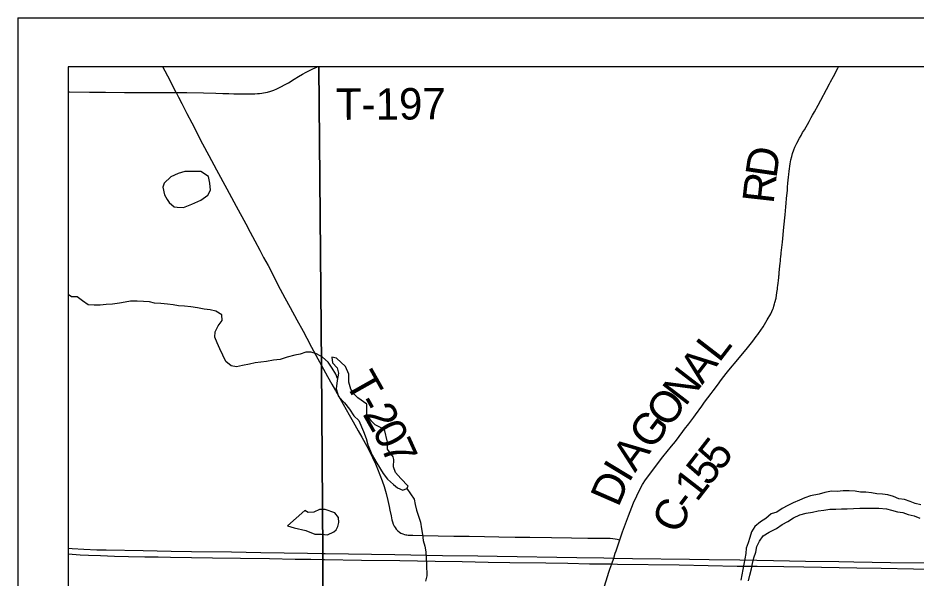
# Model space of a CAD drawing. Extents: x 0 to 34, y 0 to 22.
# Drawn here: x 12.556 to 14.178, y 15.798 to 16.81 of the extents above; entities that cross this region are included whole.
import ezdxf

# ---------------------------------------------------------------- set-up
doc = ezdxf.new("R2010")
doc.units = 0
for name, color, linetype in [('GM_X_City_Street', 7, 'Continuous'), ('GM_X_Corporation', 7, 'Continuous'), ('GM_X_County_Road', 7, 'Continuous'), ('GM_X_County_Road_Text', 7, 'Continuous'), ('GM_X_Interstate_Route', 7, 'Continuous'), ('GM_X_Major_River', 7, 'Continuous'), ('GM_X_Minor_Lake', 7, 'Continuous'), ('GM_X_Minor_River', 7, 'Continuous'), ('GM_X_Township_Road', 7, 'Continuous'), ('GM_X_Township_Road_Text', 7, 'Continuous'), ('SH_Data', 7, 'Continuous')]:
    doc.layers.add(name, color=color, linetype=linetype)

msp = doc.modelspace()

# ---------------------------------------------------------------- linework, layer by layer
at = {"layer": 'GM_X_City_Street'}
msp.add_lwpolyline([(12.842, 16.6752), (12.8266, 16.7044), (12.8217, 16.7135), (12.8174, 16.7214)], dxfattribs=at)
at = {"layer": 'GM_X_Corporation'}
for points in [[(13.1081, 15.4063), (13.1066, 15.8324), (13.1066, 15.8434), (13.1041, 16.1828), (13.0992, 16.7214), (12.6467, 16.7214), (12.6467, 12.6578)], [(13.1082, 15.4033), (13.1066, 15.8324), (13.1066, 15.8434), (13.1041, 16.1828), (13.0992, 16.7214), (12.6467, 16.7214), (12.6467, 12.6578)], [(18.6549, 16.7214), (13.0992, 16.7214), (13.1041, 16.1828), (13.1066, 15.8434), (13.1066, 15.8324), (13.1082, 15.4033)]]:
    msp.add_lwpolyline(points, dxfattribs=at)
at = {"layer": 'GM_X_County_Road'}
for points in [[(13.6429, 15.8675), (13.6477, 15.8816), (13.6584, 15.9108), (13.6677, 15.9339), (13.6734, 15.9471), (13.6789, 15.9583), (13.6838, 15.967), (13.6896, 15.9759), (13.7078, 16.0004), (13.7146, 16.0092), (13.7208, 16.0171), (13.7364, 16.0364), (13.7433, 16.0452), (13.7568, 16.063), (13.7598, 16.067), (13.7675, 16.0768), (13.7769, 16.0891), (13.7799, 16.0931), (13.7911, 16.1087), (13.7961, 16.1159), (13.8079, 16.1318), (13.8113, 16.1363), (13.8191, 16.1468), (13.8265, 16.1568), (13.835, 16.1675), (13.84, 16.1738), (13.8561, 16.1928), (13.8734, 16.214), (13.883, 16.2262), (13.8894, 16.2345), (13.892, 16.238), (13.8987, 16.2476), (13.9004, 16.2502), (13.9017, 16.2523), (13.9043, 16.2565), (13.909, 16.2645), (13.9157, 16.2757), (13.9195, 16.2841), (13.9204, 16.2864), (13.9213, 16.2893), (13.9225, 16.2935), (13.9232, 16.2958), (13.9251, 16.3036), (13.9266, 16.314), (13.9271, 16.3171), (13.9275, 16.3202), (13.9279, 16.3232), (13.9284, 16.3268), (13.9289, 16.3311), (13.9295, 16.3359), (13.93, 16.3408), (13.9303, 16.3439), (13.9305, 16.3458), (13.931, 16.35), (13.9316, 16.3556), (13.9322, 16.3623), (13.9327, 16.3666), (13.9331, 16.371), (13.9334, 16.374), (13.9339, 16.3789), (13.9343, 16.3832), (13.9345, 16.3856), (13.9367, 16.4046), (13.9394, 16.4318), (13.9413, 16.454), (13.9428, 16.4689), (13.9435, 16.4756), (13.9442, 16.4837), (13.9456, 16.4985), (13.9461, 16.5041), (13.9467, 16.5115), (13.9476, 16.5221), (13.9482, 16.527), (13.949, 16.5332), (13.9507, 16.5461), (13.9521, 16.5535), (13.9535, 16.5596), (13.9549, 16.565), (13.9572, 16.5715), (13.9592, 16.5762), (13.9628, 16.5834), (13.9677, 16.5928), (13.9704, 16.5977), (13.9729, 16.6027), (13.9763, 16.6079), (13.9849, 16.623), (13.9888, 16.63), (13.9912, 16.6343), (13.9945, 16.6403), (14.001, 16.6523), (14.006, 16.6616), (14.016, 16.6803), (14.0216, 16.6907), (14.0237, 16.6945), (14.0289, 16.7043), (14.0366, 16.7189), (14.0379, 16.7214)], [(13.6098, 15.7602), (13.61, 15.7612), (13.6125, 15.7722), (13.6149, 15.7812), (13.6161, 15.7854), (13.6173, 15.7895), (13.6184, 15.7931), (13.6234, 15.8091), (13.6252, 15.8144), (13.6284, 15.8238), (13.6319, 15.8345), (13.6348, 15.8433), (13.6362, 15.8475), (13.6429, 15.8675)]]:
    msp.add_lwpolyline(points, dxfattribs=at)
at = {"layer": 'GM_X_Interstate_Route'}
for points in [[(12.6467, 15.8522), (12.6539, 15.8517), (12.675, 15.8505), (12.6987, 15.8494), (12.7154, 15.8491), (12.7821, 15.848), (12.8324, 15.8471), (12.8697, 15.8463), (12.9419, 15.8454), (12.9944, 15.8444), (13.0788, 15.8432), (13.1045, 15.8428), (13.1068, 15.8428), (13.1108, 15.8427)], [(12.6467, 15.8419), (12.6681, 15.8404), (12.6831, 15.8396), (12.7049, 15.8388), (12.7305, 15.8378), (12.7559, 15.8372), (12.7851, 15.8367), (12.8092, 15.8364), (12.8315, 15.8361), (12.9075, 15.835), (12.9579, 15.8343), (13.0102, 15.8334), (13.0566, 15.8327), (13.0848, 15.8323), (13.1068, 15.8319), (13.1098, 15.8318)], [(13.1098, 15.8318), (13.1763, 15.8308), (13.2455, 15.8298), (13.3092, 15.829), (13.3581, 15.8281), (13.405, 15.8272), (13.4445, 15.8266), (13.5096, 15.8256), (13.5489, 15.825), (13.5883, 15.8243), (13.6284, 15.8238), (13.6385, 15.8237), (13.75, 15.8222), (13.8547, 15.82), (13.891, 15.8196), (13.9392, 15.819), (13.9755, 15.8186), (14.071, 15.8169), (14.1149, 15.8162), (14.1734, 15.8153), (14.2154, 15.8146)], [(13.1108, 15.8427), (13.2367, 15.8406), (13.3228, 15.8392), (13.3865, 15.8382), (13.4217, 15.8377), (13.5653, 15.8356), (13.614, 15.8348), (13.6319, 15.8345), (13.666, 15.8339), (13.7686, 15.8324), (13.8041, 15.8319), (13.86, 15.831), (13.8903, 15.8306), (13.9204, 15.8301), (13.9785, 15.8291), (14.0385, 15.8281), (14.0657, 15.8278), (14.1321, 15.8267), (14.1983, 15.8257)]]:
    msp.add_lwpolyline(points, dxfattribs=at)
at = {"layer": 'GM_X_Major_River'}
for points in [[(14.147, 15.9415), (14.1375, 15.9456), (14.1273, 15.9489), (14.1171, 15.9496), (14.1072, 15.9503), (14.0974, 15.9525), (14.0875, 15.9536), (14.0777, 15.9535), (14.0682, 15.9553), (14.0572, 15.9556), (14.0466, 15.9559), (14.0353, 15.9547), (14.0254, 15.955), (14.013, 15.9526), (14.0031, 15.9499), (13.9876, 15.9467), (13.9771, 15.9432), (13.9673, 15.939), (13.9563, 15.934), (13.9465, 15.9293), (13.9363, 15.9239), (13.9266, 15.9174), (13.9164, 15.9143), (13.9066, 15.9059), (13.8968, 15.8998), (13.887, 15.8917), (13.881, 15.8818), (13.8777, 15.8715), (13.8748, 15.8617), (13.871, 15.8521), (13.8704, 15.8427), (13.8685, 15.8332), (13.8671, 15.8233), (13.8653, 15.8138), (13.8631, 15.8043), (13.8613, 15.7944)], [(14.1865, 15.9308), (14.1766, 15.933), (14.1671, 15.9367), (14.1569, 15.9401), (14.147, 15.9415)], [(13.8751, 15.7932), (13.878, 15.8035), (13.8806, 15.8149), (13.8827, 15.8248), (13.8853, 15.8351), (13.8886, 15.845), (13.8903, 15.8553), (13.8952, 15.8652), (13.9019, 15.8748), (13.9128, 15.8813), (13.926, 15.8876), (13.9361, 15.8949), (13.9467, 15.9007), (13.9568, 15.9069), (13.9681, 15.9127), (13.9798, 15.9155), (13.9912, 15.9176), (14.001, 15.9196), (14.0116, 15.9208), (14.0225, 15.9229), (14.0331, 15.9226), (14.0434, 15.9235), (14.0536, 15.9232), (14.0649, 15.9241), (14.0763, 15.9246), (14.0884, 15.9244), (14.1108, 15.9247), (14.1244, 15.9233), (14.1339, 15.9211), (14.1445, 15.9178), (14.154, 15.9168), (14.1639, 15.9131), (14.1745, 15.9106), (14.1848, 15.9062)]]:
    msp.add_lwpolyline(points, dxfattribs=at)
at = {"layer": 'GM_X_Minor_Lake'}
for p, q in [((12.8288, 16.4768), (12.8383, 16.4689)), ((13.1718, 16.0828), (13.1802, 16.0627)), ((13.0742, 15.9204), (13.043, 15.8924))]:
    msp.add_line(p, q, dxfattribs=at)
for points in [[(12.8383, 16.4689), (12.8433, 16.4678), (12.855, 16.4675), (12.8701, 16.4736), (12.886, 16.4805), (12.8989, 16.4897), (12.9038, 16.4985), (12.9026, 16.5114), (12.9002, 16.5235), (12.8865, 16.5325), (12.8574, 16.5324), (12.8452, 16.5289), (12.832, 16.5228), (12.8203, 16.5117), (12.8177, 16.5045), (12.8204, 16.4901), (12.8254, 16.4821), (12.8288, 16.4768)], [(13.1802, 16.0627), (13.1848, 16.0502), (13.1879, 16.0389), (13.1956, 16.0203), (13.204, 16.0056), (13.2155, 15.987), (13.2231, 15.9772), (13.2345, 15.967), (13.2417, 15.9614), (13.2509, 15.9572), (13.2584, 15.9603), (13.2607, 15.9645), (13.2473, 15.9781), (13.2378, 15.989), (13.234, 15.9993), (13.235, 16.0126), (13.2335, 16.0171), (13.2236, 16.0311), (13.2232, 16.0436), (13.2177, 16.0667), (13.2014, 16.075), (13.1942, 16.0814), (13.1862, 16.0928), (13.1861, 16.1125), (13.1701, 16.1238), (13.1632, 16.1302), (13.1571, 16.1393), (13.1533, 16.1522), (13.1536, 16.1666), (13.1478, 16.1802), (13.1315, 16.1957), (13.1231, 16.1975), (13.1243, 16.1869), (13.1323, 16.1779), (13.135, 16.1684), (13.1324, 16.1551), (13.1306, 16.1403), (13.1348, 16.1263), (13.1455, 16.1149), (13.1546, 16.1032), (13.1627, 16.0911), (13.1718, 16.0828)], [(13.043, 15.8924), (13.0547, 15.8891), (13.076, 15.884), (13.0923, 15.8776), (13.1044, 15.8774), (13.115, 15.8763), (13.1263, 15.8817), (13.1305, 15.8855), (13.1338, 15.8912), (13.1353, 15.8988), (13.1348, 15.9076), (13.1283, 15.9162), (13.1109, 15.9222), (13.1003, 15.9221), (13.0901, 15.9175), (13.0803, 15.9166), (13.0742, 15.9204)]]:
    msp.add_lwpolyline(points, dxfattribs=at)
at = {"layer": 'GM_X_Minor_River'}
for points in [[(13.1331, 16.1585), (13.1301, 16.1668), (13.1236, 16.1774), (13.116, 16.1884), (13.1057, 16.1975), (13.0954, 16.2031), (13.0856, 16.2061), (13.0757, 16.206), (13.0659, 16.2029), (13.056, 16.2006), (13.0424, 16.1971), (13.0295, 16.1933), (13.0174, 16.1917), (13.0049, 16.1897), (12.9947, 16.1885), (12.9841, 16.187), (12.9742, 16.1843), (12.9613, 16.1823), (12.9507, 16.18), (12.9413, 16.1814), (12.9314, 16.1893), (12.926, 16.2011), (12.9206, 16.2124), (12.916, 16.2234), (12.9118, 16.2333), (12.9122, 16.2431), (12.9178, 16.2538), (12.9249, 16.2637), (12.9241, 16.2736), (12.9135, 16.2803), (12.9033, 16.2829), (12.8923, 16.284), (12.8805, 16.2866), (12.8684, 16.2881), (12.8566, 16.2891), (12.846, 16.2902), (12.8365, 16.2917), (12.8259, 16.2928), (12.8138, 16.2939), (12.8028, 16.2946), (12.7933, 16.2972), (12.783, 16.2979), (12.7713, 16.2982), (12.7595, 16.2981), (12.7493, 16.2966), (12.7395, 16.2946), (12.727, 16.293), (12.7152, 16.2922), (12.7042, 16.2914), (12.6936, 16.291), (12.683, 16.2917), (12.6724, 16.2988), (12.6628, 16.3064), (12.6526, 16.3059), (12.6467, 16.3102)], [(13.2584, 15.9603), (13.2716, 15.9409), (13.2736, 15.931), (13.2759, 15.9208), (13.2794, 15.9102), (13.2829, 15.8992), (13.2849, 15.8871), (13.2865, 15.8772), (13.2877, 15.8663), (13.2908, 15.8557), (13.2924, 15.8454), (13.2932, 15.8352), (13.2941, 15.8227), (13.2942, 15.8026), (13.292, 15.7927)]]:
    msp.add_lwpolyline(points, dxfattribs=at)
at = {"layer": 'GM_X_Township_Road'}
for points in [[(12.842, 16.6752), (12.861, 16.675), (12.8913, 16.6744), (12.9131, 16.6738), (12.9257, 16.6734), (12.9368, 16.6731), (12.9459, 16.6729), (12.955, 16.6727), (12.9625, 16.6725), (12.9701, 16.6725), (12.9787, 16.6726), (12.9836, 16.6729), (12.9884, 16.6731), (12.9925, 16.6734), (12.9962, 16.6739), (12.9996, 16.6744), (13.0032, 16.6751), (13.0069, 16.676), (13.0126, 16.6776), (13.0179, 16.6796), (13.0233, 16.6819), (13.0281, 16.6842), (13.0322, 16.6862), (13.0376, 16.689), (13.0444, 16.6929), (13.0547, 16.699), (13.0628, 16.7039), (13.0701, 16.7082), (13.0765, 16.7119), (13.0836, 16.7155), (13.0885, 16.7179), (13.093, 16.7199), (13.0959, 16.7212), (13.0966, 16.7214)], [(12.6467, 16.6763), (12.649, 16.6763), (12.6849, 16.676), (12.714, 16.6757), (12.7483, 16.6754), (12.7662, 16.6752), (12.842, 16.6752)], [(12.842, 16.6752), (12.8462, 16.6669), (12.8522, 16.6552), (12.8612, 16.6375), (12.8698, 16.6206), (12.8895, 16.5826), (12.9006, 16.5614), (12.9146, 16.5354), (12.9333, 16.501), (12.9503, 16.4697), (12.9675, 16.438), (12.9755, 16.4229), (12.9838, 16.4071), (12.9927, 16.3905), (12.9996, 16.3775), (13.0076, 16.3626), (13.013, 16.3527), (13.0195, 16.3398), (13.0295, 16.32), (13.0381, 16.3042), (13.0478, 16.2871), (13.0598, 16.2648), (13.0708, 16.2441), (13.0777, 16.2315), (13.0864, 16.2154), (13.0977, 16.1945), (13.1043, 16.1822)], [(13.1043, 16.1822), (13.1153, 16.1623), (13.123, 16.1483), (13.1292, 16.1372), (13.1376, 16.1222), (13.1541, 16.0929), (13.1611, 16.0805), (13.1703, 16.0645), (13.1771, 16.0528), (13.1832, 16.042), (13.1898, 16.0296), (13.1965, 16.0158), (13.2015, 16.0048), (13.2054, 15.9956), (13.2097, 15.9846), (13.2135, 15.9742), (13.2171, 15.9635), (13.2207, 15.9509), (13.224, 15.9386), (13.2265, 15.9277), (13.2279, 15.921), (13.2298, 15.9109), (13.2315, 15.9032), (13.2323, 15.8999), (13.2336, 15.8957), (13.2353, 15.8923), (13.237, 15.8895), (13.2392, 15.8868), (13.2418, 15.8838), (13.245, 15.8812), (13.2476, 15.8795), (13.251, 15.878), (13.254, 15.877), (13.2564, 15.8765), (13.2584, 15.8762), (13.2606, 15.8759), (13.2635, 15.8758), (13.2693, 15.8756), (13.2863, 15.8752), (13.315, 15.8747), (13.3429, 15.8742), (13.3539, 15.874)], [(13.3539, 15.874), (13.3711, 15.8737), (13.3985, 15.8732), (13.4247, 15.8728), (13.4537, 15.8724), (13.4805, 15.872), (13.5193, 15.8714), (13.5558, 15.871), (13.5855, 15.8706), (13.6184, 15.8702), (13.6258, 15.8701), (13.6302, 15.8699), (13.6345, 15.8693), (13.6381, 15.8687), (13.6429, 15.8675)]]:
    msp.add_lwpolyline(points, dxfattribs=at)
at = {"layer": 'SH_Data'}
for q in [(19.556, 16.8098), (12.556, 9.8098)]:
    msp.add_line((12.556, 16.8098), q, dxfattribs=at)

# ---------------------------------------------------------------- texts
at = {"layer": 'GM_X_County_Road_Text'}
for s, rotation, p in [('D', 81.6911, (13.9256, 16.5189)), ('R', 83.5818, (13.9205, 16.473)), ('L', 52.387, (13.8222, 16.1859)), ('A', 52.3872, (13.7917, 16.1463)), ('N', 52.3846, (13.7612, 16.1067)), ('O', 52.3819, (13.7307, 16.0671)), ('G', 52.4547, (13.7002, 16.0275)), ('A', 53.3261, (13.6705, 15.9876)), ('5', 52.1497, (13.8248, 15.9895)), ('5', 52.1944, (13.8034, 15.9619)), ('I', 58.7832, (13.6592, 15.9688)), ('D', 66.4551, (13.6401, 15.9247)), ('1', 52.2797, (13.782, 15.9342)), ('-', 53.0911, (13.7681, 15.9157)), ('C', 66.0942, (13.7509, 15.876))]:
    msp.add_text(s, height=0.0568, rotation=rotation, dxfattribs=at).set_placement(p)
at = {"layer": 'GM_X_Township_Road_Text'}
for s, height, rotation, p in [('T-197', 0.05682, 0.2746, (13.1303, 16.6257)), ('T', 0.0568, 299.3855, (13.1453, 16.1517)), ('-', 0.0568, 299.395, (13.1661, 16.1147)), ('2', 0.0568, 299.5246, (13.1776, 16.0945)), ('0', 0.0568, 298.314, (13.1945, 16.0645)), ('7', 0.0568, 294.425, (13.2105, 16.0349))]:
    msp.add_text(s, height=height, rotation=rotation, dxfattribs=at).set_placement(p)

doc.saveas('drawing.dxf')
